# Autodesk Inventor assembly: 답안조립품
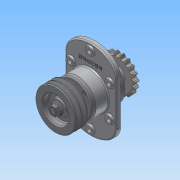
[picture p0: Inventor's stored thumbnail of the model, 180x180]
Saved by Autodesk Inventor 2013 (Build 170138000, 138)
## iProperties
Created: 2015-02
Part Number: 답안조립품
Document SubType Name: Assembly
Designer: Administrator
Author: Administrator
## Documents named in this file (12)
- C:\Users\Administrator\Desktop\450208V1006\답안조립품.iam
- C:\Users\Administrator\Desktop\450208V1006\본체.ipt
- C:\Users\Administrator\Desktop\450208V1006\2-커버.ipt
- C:\Users\Administrator\Desktop\450208V1006\3-축.ipt
- C:\Users\Administrator\Desktop\450208V1006\4-V벨트풀리.ipt
- C:\Users\Administrator\Desktop\450208V1006\5-체인 스프로킷.ipt
- C:\Users\Administrator\Desktop\450208V1006\6-베어링 6206.ipt
- C:\Users\Administrator\Desktop\450208V1006\7-부시.ipt
- C:\Users\Administrator\Desktop\450208V1006\8-오일실 30x42.ipt
- C:\Users\Administrator\Desktop\450208V1006\9-M16-너트.ipt
- C:\Users\Administrator\Desktop\450208V1006\10-M6.ipt
- C:\Users\Administrator\Desktop\450208V1006\11-키 6x6.ipt
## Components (22 placed, 10 different names)
1. 2-커버:1
2. 3-축:1
3. 4-V벨트풀리:1
4. 5-체인 스프로킷:1
5. 6-베어링 6206:1
6. 7-부시:1
7. 8-8-오일실 30x42:1
8. 9-M16 너트:1
9. 11-키 6x6:1
10. 11-키 6x6:2
11. 6-베어링 6206:2
12. 2-커버:2
13. 8-8-오일실 30x42:2
14. 9-M16 너트:2
15. 10-M6:1
16. 10-M6:3
17. 10-M6:4
18. 10-M6:5
19. 10-M6:2
20. 10-M6:6
21. 10-M6:7
22. 10-M6:8
